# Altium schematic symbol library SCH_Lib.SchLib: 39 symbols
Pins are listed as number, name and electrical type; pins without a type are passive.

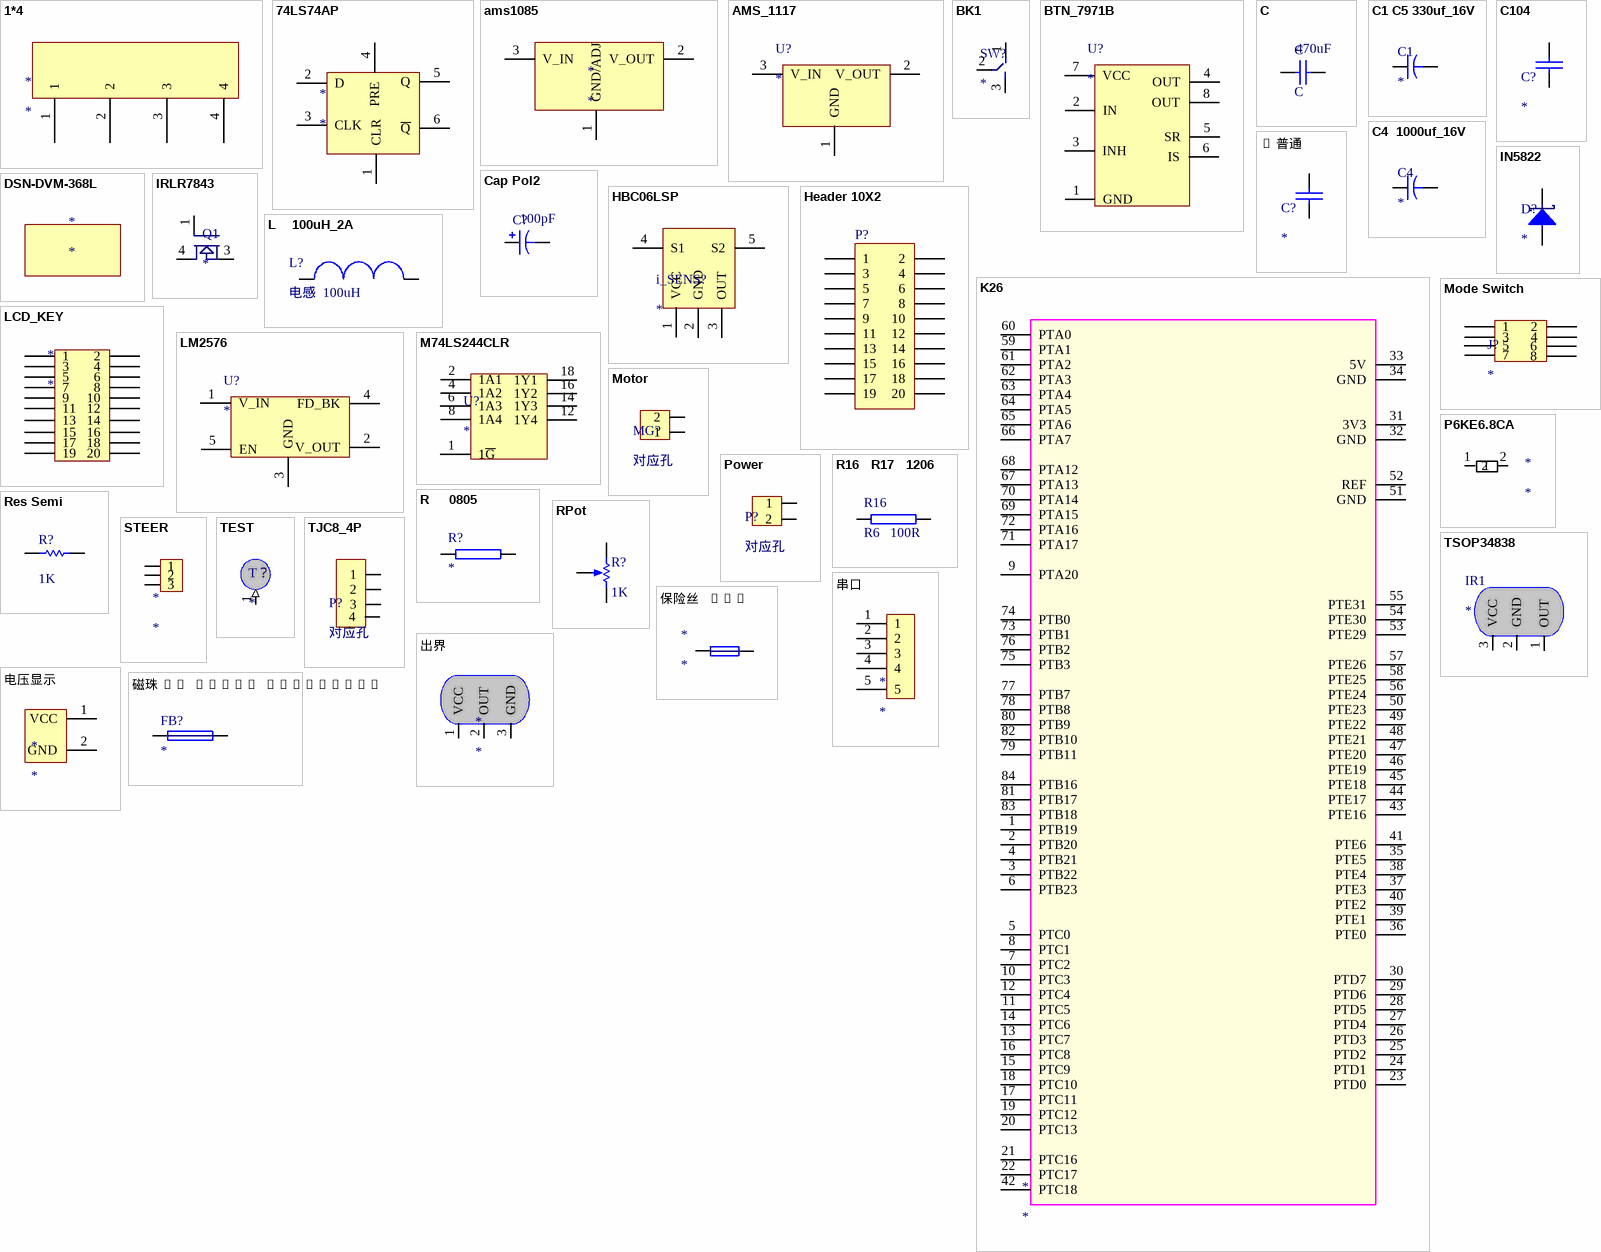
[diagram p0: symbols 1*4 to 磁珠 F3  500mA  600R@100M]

## 1*4
designator *
footprint HDR1X4 (Connector; Header; 4 Position)
pins: 1, 2, 3, 4

## 74LS74AP
designator *
footprint 74LS74AP
pins: 1 CLR, 2 D, 3 CLK, 4 PRE, 5 Q, 6 ~{Q}

## ams1085
designator *
footprint AMS 1085CD
pins: 1 GND/ADJ, 2 V_OUT, 3 V_IN

## AMS_1117
designator U?
footprint AMS_1117
pins: 1 GND, 2 V_OUT, 3 V_IN

## BK1
designator SW?
footprint BK1
pins: 1, 2, 3

## BTN_7971B
designator U?
footprint BTN_7971B
pins: 1 GND, 2 IN, 3 INH, 4 OUT, 5 SR, 6 IS, 7 VCC, 8 OUT

## C
designator C  value 470uF
Capacitor
footprint RAD-0.3 (Radial Cap, Thru-Hole; 2 Leads; 0.3 in Pin Spacing)
footprint CAPR2.54-5.1x3.2 (Capacitor, Ceramic, Thru-Hole, Dipped Radial; Body 5.1 x 3.2 mm (WxT) Pin Spacing 2.54 mm (typ))
footprint CAPR5.08-7.8x3.2 (Capacitor, Ceramic, Thru-Hole, Dipped Radial; Body 7.8 x 3.2 mm (WxT) Pin Spacing 5.08 mm (typ))
simulation model CAP (Capacitor)
signal-integrity model Cap
footprint C
pins: 1, 2

## C1 C5 330uf_16V
designator C1
footprint C1 C5 330uf_16V
pins: 1, 2

## C4  1000uf_16V
designator C4
footprint C4 1000uf_16v
pins: 1, 2

## C104
designator C?
footprint C104
pins: 1, 2

## C 普通
designator C?
footprint C普通
footprint C
pins: 1, 2

## Cap Pol2
designator C?  value 100pF
Polarized Capacitor (Axial)
footprint C普通
footprint C
pins: 1, 2
1 alternate drawing of the same symbol

## DSN-DVM-368L
designator *
footprint DSN-DVM-368L

## HBC06LSP
designator i_SENS?
footprint HBC06LSP
pins: 1 VCC, 2 GND, 3 OUT, 4 S1, 5 S2

## Header 10X2
designator P?
Header, 10-Pin, Dual row
footprint HDR2X10 (Connector; Header; 10x2 Position)
pins: 1, 2, 3, 4, 5, 6, 7, 8, 9, 10, 11, 12, 13, 14, 15, 16, 17, 18, 19, 20

## IN5822
designator D?
footprint IN5822
pins: 1, 2

## IRLR7843
designator Q1
footprint IRLR7843
pins: 1, 3, 4

## K26
designator *
footprint KL26
pins: 1 PTB19, 2 PTB20, 3 PTB22, 4 PTB21, 5 PTC0, 6 PTB23, 7 PTC2, 8 PTC1, 9 PTA20, 10 PTC3, 11 PTC5, 12 PTC4, 13 PTC7, 14 PTC6, 15 PTC9, 16 PTC8, 17 PTC11, 18 PTC10, 19 PTC12, 20 PTC13, 21 PTC16, 22 PTC17, 23 PTD0, 24 PTD1, 25 PTD2, 26 PTD3, 27 PTD4, 28 PTD5, 29 PTD6, 30 PTD7, 31 3V3, 32 GND, 33 5V, 34 GND, 35 PTE5, 36 PTE0, 37 PTE3, 38 PTE4, 39 PTE1, 40 PTE2, 41 PTE6, 42 PTC18, 43 PTE16, 44 PTE17, 45 PTE18, 46 PTE19, 47 PTE20, 48 PTE21, 49 PTE22, 50 PTE23, 51 GND, 52 REF, 53 PTE29, 54 PTE30, 55 PTE31, 56 PTE24, 57 PTE26, 58 PTE25, 59 PTA1, 60 PTA0, 61 PTA2, 62 PTA3, 63 PTA4, 64 PTA5, 65 PTA6, 66 PTA7, 67 PTA13, 68 PTA12, 69 PTA15, 70 PTA14, 71 PTA17, 72 PTA16, 73 PTB1, 74 PTB0, 75 PTB3, 76 PTB2, 77 PTB7, 78 PTB8, 79 PTB11, 80 PTB9, 81 PTB17, 82 PTB10, 83 PTB18, 84 PTB16

## L    100uH_2A
designator L?, comment 电感  100uH
footprint L 1000uH_2A
pins: 1, 2

## LCD_KEY
designator *
footprint LCD_KEY (LCD    长5cm，宽3.4cm)
pins: 1, 2, 3, 4, 5, 6, 7, 8, 9, 10, 11, 12, 13, 14, 15, 16, 17, 18, 19, 20

## LM2576
designator U?
footprint LM2576
pins: 1 V_IN, 2 V_OUT, 3 GND, 4 FD_BK, 5 EN

## M74LS244CLR
designator U?
footprint M74LS244C1R
footprint M74LS244C1R
pins: 1 1~{G}, 2 1A1, 4 1A2, 6 1A3, 8 1A4, 12 1Y4, 14 1Y3, 16 1Y2, 18 1Y1

## Mode Switch
designator J?
footprint Mode Switch
pins: 1, 2, 3, 4, 5, 6, 7, 8

## Motor
designator MG?, comment 对应孔
footprint Motor
pins: 1, 2

## P6KE6.8CA
designator *
footprint P6KE6.8CA
pins: 1, 2

## Power
designator P?, comment 对应孔
footprint Power
pins: 1, 2

## R16   R17   1206
designator R16, comment R6   100R
footprint R16  R17    1206
pins: 1, 2

## R     0805
designator R?
footprint R  0805
pins: 1, 2

## Res Semi
designator R?  value 1K
Semiconductor Resistor
footprint R (Resistor; 2 Leads)
pins: 1, 2

## RPot
designator R?  value 1K
Potentiometer; Sim Note: Enter the Resistance value and the set point into parameter fields.; Set Position: 0.5
footprint VR5 (Potentiometer; 3 Leads)
pins: 1 TOP, 2 TAP, 3 BOT
1 alternate drawing of the same symbol

## STEER
designator *
footprint STEER
pins: 1, 2, 3

## TEST
designator T？
footprint TEST
pins: 1 (in)

## TJC8_4P
designator P?, comment 对应孔
footprint TJC8_4P
pins: 1, 2, 3, 4

## TSOP34838
designator IR1
footprint TOSP34838
pins: 1 OUT, 2 GND, 3 VCC

## 串口
designator *
footprint HDR1X4H (Connector; Header; 4 Position; Right Angle)
pins: 1, 2, 3, 4, 5

## 保险丝   15A
designator *
footprint 保险丝  15A
pins: 1, 2

## 出界
designator *
pins: 1 VCC, 2 OUT, 3 GND

## 电压显示
designator *
footprint HDR1X2 (Connector; Header; 2 Position)
pins: 1 VCC, 2 GND

## 磁珠 F3  500mA  600R@100M
designator FB?
footprint 磁珠 F3 600@100M
pins: 1, 2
